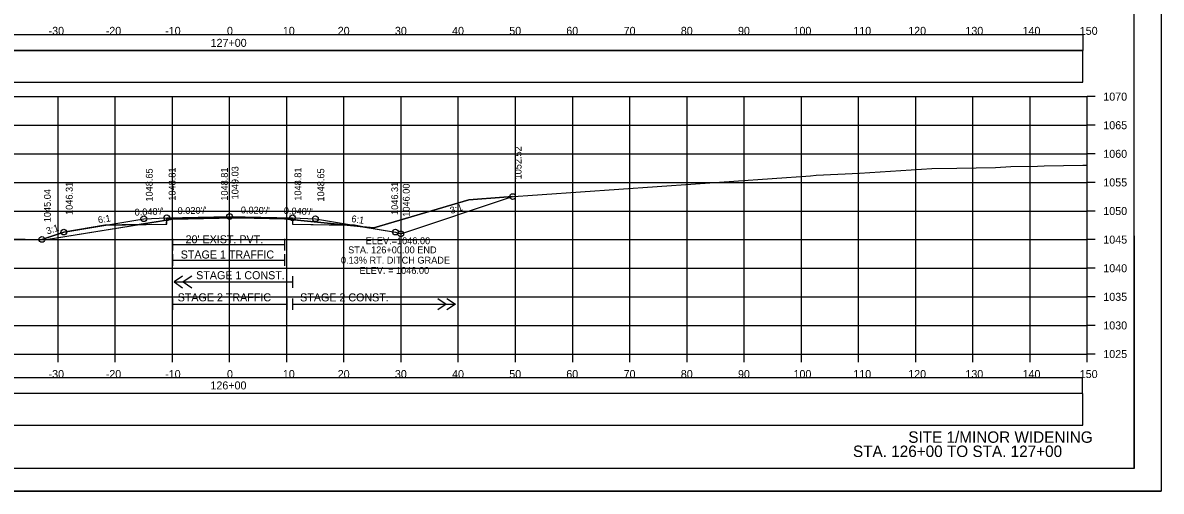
# Model space of a CAD drawing. Extents: x 1370565 to 1374448, y 301010 to 304637.
# Drawn here: x 1370698.9 to 1370898, y 303783.9 to 303865.8 of the extents above; entities that cross this region are included whole.
import ezdxf

# ---------------------------------------------------------------- set-up
doc = ezdxf.new("R2010")
doc.units = 0
for name, color, linetype in [('R_Alt Surface', 7, 'Continuous'), ('R_Axis', 7, 'Continuous'), ('R_Axis Annot', 7, 'Continuous'), ('R_Border', 7, 'Continuous'), ('R_Contours', 7, 'Continuous'), ('R_Draft', 7, 'Continuous'), ('R_Drive', 7, 'Continuous'), ('R_Exist Surface', 7, 'Continuous'), ('R_Fin Surface', 7, 'Continuous'), ('R_Grid', 7, 'Continuous'), ('R_No Plot', 7, 'Continuous'), ('R_Water', 7, 'Continuous'), ('R_Xsect Elev', 7, 'Continuous'), ('R_Xsect Slope', 7, 'Continuous')]:
    doc.layers.add(name, color=color, linetype=linetype)

msp = doc.modelspace()

# ---------------------------------------------------------------- linework, layer by layer
at = {"layer": 'R_Alt Surface'}
for points in [[(1370713.19, 303830.38), (1370724.03, 303830.59), (1370724.02, 303830.59), (1370724.03, 303831.51), (1370735.03, 303831.73), (1370746.03, 303831.51), (1370746.04, 303830.59), (1370746.03, 303830.59), (1370756.87, 303830.38)], [(1370726.82, 303821.47), (1370725.32, 303820.47), (1370726.82, 303819.47)], [(1370728.42, 303821.47), (1370726.92, 303820.47), (1370728.42, 303819.47)], [(1370725.32, 303820.47), (1370746.03, 303820.47)], [(1370725.03, 303817.6), (1370725.03, 303815.6)], [(1370745.03, 303817.6), (1370745.03, 303815.6)], [(1370746.03, 303817.6), (1370746.03, 303815.6)], [(1370746.03, 303817.6), (1370746.03, 303815.6)], [(1370771.42, 303817.6), (1370772.92, 303816.6), (1370771.42, 303815.6)], [(1370773.02, 303817.6), (1370774.52, 303816.6), (1370773.02, 303815.6)], [(1370725.03, 303816.6), (1370745.03, 303816.6)], [(1370746.03, 303816.6), (1370774.52, 303816.6)]]:
    msp.add_lwpolyline(points, dxfattribs=at)
at = {"layer": 'R_Axis'}
for p, q in [((1370885.03, 303807.87), (1370885.03, 303852.87)), ((1370886.43, 303852.87), (1370885.03, 303852.87)), ((1370886.43, 303847.87), (1370885.03, 303847.87)), ((1370886.43, 303842.87), (1370885.03, 303842.87)), ((1370886.43, 303837.87), (1370885.03, 303837.87)), ((1370886.43, 303832.87), (1370885.03, 303832.87)), ((1370886.43, 303827.87), (1370885.03, 303827.87)), ((1370886.43, 303822.87), (1370885.03, 303822.87)), ((1370886.43, 303817.87), (1370885.03, 303817.87)), ((1370886.43, 303812.87), (1370885.03, 303812.87)), ((1370585.03, 303807.87), (1370885.03, 303807.87)), ((1370705.03, 303806.47), (1370705.03, 303807.87)), ((1370715.03, 303806.47), (1370715.03, 303807.87)), ((1370725.03, 303806.47), (1370725.03, 303807.87)), ((1370735.03, 303806.47), (1370735.03, 303807.87)), ((1370745.03, 303806.47), (1370745.03, 303807.87)), ((1370755.03, 303806.47), (1370755.03, 303807.87)), ((1370765.03, 303806.47), (1370765.03, 303807.87)), ((1370775.03, 303806.47), (1370775.03, 303807.87)), ((1370785.03, 303806.47), (1370785.03, 303807.87)), ((1370795.03, 303806.47), (1370795.03, 303807.87)), ((1370805.03, 303806.47), (1370805.03, 303807.87)), ((1370815.03, 303806.47), (1370815.03, 303807.87)), ((1370825.03, 303806.47), (1370825.03, 303807.87)), ((1370835.03, 303806.47), (1370835.03, 303807.87)), ((1370845.03, 303806.47), (1370845.03, 303807.87)), ((1370855.03, 303806.47), (1370855.03, 303807.87)), ((1370865.03, 303806.47), (1370865.03, 303807.87)), ((1370875.03, 303806.47), (1370875.03, 303807.87)), ((1370885.03, 303806.47), (1370885.03, 303807.87)), ((1370886.43, 303807.87), (1370885.03, 303807.87))]:
    msp.add_line(p, q, dxfattribs=at)
for points in [[(1370725.02, 303827.99), (1370725.02, 303825.99)], [(1370725.02, 303826.99), (1370744.65, 303826.99)], [(1370744.65, 303827.99), (1370744.65, 303825.99)], [(1370725.02, 303825.3), (1370725.02, 303823.3)], [(1370744.65, 303825.3), (1370744.65, 303823.3)], [(1370725.02, 303824.3), (1370744.65, 303824.3)], [(1370746.03, 303821.47), (1370746.03, 303819.47)]]:
    msp.add_lwpolyline(points, dxfattribs=at)
at = {"layer": 'R_Border'}
for q in [(1370893.21, 303993.33), (1370577.03, 303787.87)]:
    msp.add_line((1370893.21, 303787.87), q, dxfattribs=at)
at = {"layer": 'R_Contours'}
for p, q in [((1370725.02, 303831.53), (1370724.03, 303831.51)), ((1370724.03, 303831.51), (1370724.03, 303831.28)), ((1370724.03, 303831.28), (1370725.02, 303831.44)), ((1370724.03, 303830.59), (1370724.03, 303831.28)), ((1370733.23, 303831.65), (1370725.02, 303831.53)), ((1370725.02, 303831.44), (1370733.23, 303831.64)), ((1370746.03, 303831.51), (1370744.69, 303831.53)), ((1370744.69, 303831.53), (1370746.03, 303831.38)), ((1370746.03, 303831.38), (1370746.03, 303831.51)), ((1370746.03, 303831.38), (1370746.04, 303830.59)), ((1370706.03, 303829.18), (1370702.21, 303827.91)), ((1370713.19, 303830.38), (1370706.03, 303829.18)), ((1370719.19, 303830.5), (1370713.19, 303830.38)), ((1370719.19, 303830.5), (1370724.03, 303830.59)), ((1370746.04, 303830.59), (1370755.65, 303830.4)), ((1370756.87, 303830.38), (1370755.65, 303830.4)), ((1370755.65, 303830.4), (1370756.86, 303830.28)), ((1370756.86, 303830.28), (1370758.35, 303830.13)), ((1370758.35, 303830.13), (1370756.87, 303830.38)), ((1370758.35, 303830.13), (1370764.03, 303829.18))]:
    msp.add_line(p, q, dxfattribs=at)
for points in [[(1370784.53, 303835.39), (1370782.99, 303835.28), (1370776.89, 303834.84), (1370774.9, 303834.22), (1370760.23, 303829.94), (1370758.35, 303830.13)], [(1370764.03, 303829.18), (1370764.97, 303828.87), (1370784.53, 303835.39)], [(1370724.03, 303831.28), (1370721.08, 303830.8), (1370719.19, 303830.5)], [(1370725.02, 303831.44), (1370725.02, 303831.53)], [(1370725.02, 303831.53), (1370725.02, 303831.44)], [(1370733.23, 303831.64), (1370733.23, 303831.65)], [(1370755.65, 303830.4), (1370747.51, 303831.22), (1370746.03, 303831.38)], [(1370702.21, 303827.91), (1370702.93, 303827.9), (1370719.19, 303830.5)], [(1370756.87, 303830.38), (1370756.86, 303830.28)], [(1370756.86, 303830.28), (1370756.87, 303830.38)]]:
    msp.add_lwpolyline(points, dxfattribs=at)
at = {"layer": 'R_Drive'}
for points in [[(1370585.87, 303860.96), (1370884.29, 303860.96), (1370884.29, 303863.67), (1370585.87, 303863.67)], [(1370585.82, 303855.39), (1370884.24, 303855.39), (1370884.24, 303860.91), (1370585.82, 303860.91)], [(1370585.76, 303801.02), (1370884.18, 303801.02), (1370884.18, 303803.73), (1370585.76, 303803.73)], [(1370585.82, 303795.44), (1370884.24, 303795.44), (1370884.24, 303800.96), (1370585.82, 303800.96)]]:
    msp.add_lwpolyline(points, close=True, dxfattribs=at)
at = {"layer": 'R_Exist Surface'}
msp.add_lwpolyline([(1370695.06, 303828.04), (1370701.38, 303827.92), (1370702.93, 303827.9), (1370721.08, 303830.8), (1370725.02, 303831.44), (1370733.23, 303831.64), (1370734.98, 303831.68), (1370736.71, 303831.66), (1370744.65, 303831.53), (1370747.51, 303831.22), (1370760.23, 303829.94), (1370774.9, 303834.22), (1370776.89, 303834.84), (1370782.99, 303835.28), (1370836.64, 303839.03), (1370837.62, 303839.16), (1370845.21, 303839.49), (1370857.86, 303840.3), (1370862.22, 303840.39), (1370868.99, 303840.49), (1370871.68, 303840.67), (1370876.31, 303840.73), (1370877.5, 303840.76), (1370884.24, 303840.89), (1370885.03, 303840.9)], dxfattribs=at)
at = {"layer": 'R_Fin Surface'}
msp.add_lwpolyline([(1370702.21, 303827.91), (1370706.03, 303829.18), (1370720.03, 303831.52), (1370724.03, 303831.68), (1370735.03, 303831.9), (1370746.03, 303831.68), (1370750.03, 303831.52), (1370764.03, 303829.18), (1370764.97, 303828.87), (1370784.53, 303835.39)], dxfattribs=at)
at = {"layer": 'R_Grid'}
for p, q in [((1370585.03, 303852.87), (1370885.03, 303852.87)), ((1370705.03, 303807.87), (1370705.03, 303852.87)), ((1370715.03, 303807.87), (1370715.03, 303852.87)), ((1370725.03, 303807.87), (1370725.03, 303852.87)), ((1370735.03, 303807.87), (1370735.03, 303852.87)), ((1370745.03, 303807.87), (1370745.03, 303852.87)), ((1370755.03, 303807.87), (1370755.03, 303852.87)), ((1370765.03, 303807.87), (1370765.03, 303852.87)), ((1370775.03, 303807.87), (1370775.03, 303852.87)), ((1370785.03, 303807.87), (1370785.03, 303852.87)), ((1370795.03, 303807.87), (1370795.03, 303852.87)), ((1370805.03, 303807.87), (1370805.03, 303852.87)), ((1370815.03, 303807.87), (1370815.03, 303852.87)), ((1370825.03, 303807.87), (1370825.03, 303852.87)), ((1370835.03, 303807.87), (1370835.03, 303852.87)), ((1370845.03, 303807.87), (1370845.03, 303852.87)), ((1370855.03, 303807.87), (1370855.03, 303852.87)), ((1370865.03, 303807.87), (1370865.03, 303852.87)), ((1370875.03, 303807.87), (1370875.03, 303852.87)), ((1370885.03, 303807.87), (1370885.03, 303852.87)), ((1370585.03, 303847.87), (1370885.03, 303847.87)), ((1370585.03, 303842.87), (1370885.03, 303842.87)), ((1370585.03, 303837.87), (1370885.03, 303837.87)), ((1370585.03, 303832.87), (1370885.03, 303832.87)), ((1370585.03, 303827.87), (1370885.03, 303827.87)), ((1370585.03, 303822.87), (1370885.03, 303822.87)), ((1370585.03, 303817.87), (1370885.03, 303817.87)), ((1370585.03, 303812.87), (1370885.03, 303812.87)), ((1370585.03, 303807.87), (1370885.03, 303807.87))]:
    msp.add_line(p, q, dxfattribs=at)
at = {"layer": 'R_No Plot'}
msp.add_line((1370564.63, 303783.89), (1370897.96, 303783.89), dxfattribs=at)
for points in [[(1370564.62, 303997.22), (1370897.96, 303997.22), (1370897.96, 303783.89), (1370564.62, 303783.89)], [(1370810.95, 303993.33), (1370830.57, 303993.33), (1370830.57, 303983.45), (1370846.68, 303983.45), (1370869.88, 303983.45), (1370869.88, 303950.78), (1370893.09, 303950.78), (1370893.21, 303787.87), (1370577.03, 303787.87), (1370577.03, 303993.33)]]:
    msp.add_lwpolyline(points, close=True, dxfattribs=at)
for centre in [(1370784.53, 303835.39), (1370720.03, 303831.52), (1370724.03, 303831.68), (1370735.03, 303831.9), (1370746.03, 303831.68), (1370750.03, 303831.52), (1370706.03, 303829.18), (1370764.03, 303829.18), (1370764.97, 303828.87), (1370702.21, 303827.91)]:
    msp.add_circle(centre, 0.5, dxfattribs=at)
at = {"layer": 'R_Xsect Elev'}
msp.add_line((1370735.03, 303831.68), (1370735.03, 303841.68), dxfattribs=at)

# ---------------------------------------------------------------- texts
at = {"layer": 'R_Axis Annot'}
for s, p in [('-30', (1370703.37, 303863.67)), ('-20', (1370713.37, 303863.67)), ('-10', (1370723.76, 303863.67)), ('0', (1370734.57, 303863.67)), ('10', (1370744.34, 303863.67)), ('20', (1370753.94, 303863.67)), ('30', (1370763.94, 303863.67)), ('40', (1370773.94, 303863.67)), ('50', (1370783.94, 303863.67)), ('60', (1370793.91, 303863.67)), ('70', (1370803.94, 303863.67)), ('80', (1370813.94, 303863.67)), ('90', (1370823.94, 303863.67)), ('100', (1370833.65, 303863.67)), ('110', (1370844.11, 303863.67)), ('120', (1370853.71, 303863.67)), ('130', (1370863.71, 303863.67)), ('140', (1370873.71, 303863.67)), ('150', (1370883.71, 303863.67)), ('127+00', (1370731.71, 303861.57)), ('1070', (1370887.83, 303852.17)), ('1065', (1370887.83, 303847.17)), ('1060', (1370887.83, 303842.17)), ('1055', (1370887.83, 303837.17)), ('1050', (1370887.83, 303832.17)), ("20' EXIST. PVT.", (1370727.33, 303827.23)), ('1045', (1370887.83, 303827.17)), ('1040', (1370887.83, 303822.17)), ('1035', (1370887.83, 303817.17)), ('1030', (1370887.83, 303812.17)), ('1025', (1370887.83, 303807.17)), ('-30', (1370703.37, 303803.67)), ('-20', (1370713.37, 303803.67)), ('-10', (1370723.76, 303803.67)), ('0', (1370734.57, 303803.67)), ('10', (1370744.34, 303803.67)), ('20', (1370753.94, 303803.67)), ('30', (1370763.94, 303803.67)), ('40', (1370773.94, 303803.67)), ('50', (1370783.94, 303803.67)), ('60', (1370793.91, 303803.67)), ('70', (1370803.94, 303803.67)), ('80', (1370813.94, 303803.67)), ('90', (1370823.94, 303803.67)), ('100', (1370833.65, 303803.67)), ('110', (1370844.11, 303803.67)), ('120', (1370853.71, 303803.67)), ('130', (1370863.71, 303803.67)), ('140', (1370873.71, 303803.67)), ('150', (1370883.71, 303803.67)), ('126+00', (1370731.68, 303801.68))]:
    msp.add_text(s, height=1.4, dxfattribs=at).set_placement(p)
at = {"layer": 'R_Draft'}
for s, p in [('SITE 1/MINOR WIDENING', (1370853.72, 303792.35)), ('STA. 126+00 TO STA. 127+00', (1370844.05, 303789.87))]:
    msp.add_text(s, height=2, dxfattribs=at).set_placement(p)
at = {"layer": 'R_Water'}
for s, p in [('STAGE 1 TRAFFIC', (1370726.48, 303824.57)), ('STAGE 1 CONST.', (1370729.18, 303820.95)), ('STAGE 2 TRAFFIC', (1370725.95, 303817.08)), ('STAGE 2 CONST.', (1370747.37, 303817.07))]:
    msp.add_text(s, height=1.4, dxfattribs=at).set_placement(p)
at = {"layer": 'R_Xsect Elev'}
for s, p in [('1052.52', (1370786.08, 303838.39)), ('1049.03', (1370736.58, 303834.9)), ('1048.65', (1370721.58, 303834.52)), ('1048.81', (1370725.58, 303834.68)), ('1048.81', (1370734.73, 303834.68)), ('1048.81', (1370747.58, 303834.68)), ('1048.65', (1370751.58, 303834.52)), ('1045.04', (1370703.76, 303830.91)), ('1046.31', (1370707.58, 303832.18)), ('1046.31', (1370764.5, 303832.18)), ('1046.00', (1370766.52, 303831.87))]:
    msp.add_text(s, height=1.2, rotation=90, dxfattribs=at).set_placement(p)
for s, p in [('STA. 126+00.00 END ', (1370755.76, 303825.48)), ('ELEV.=1046.00', (1370758.82, 303827.07)), ('0.13% RT. DITCH GRADE', (1370754.5, 303823.68)), ('ELEV. = 1046.00', (1370757.75, 303821.88))]:
    msp.add_text(s, height=1.2, dxfattribs=at).set_placement(p)
at = {"layer": 'R_Xsect Slope'}
for s, rotation, p in [("0.040'/'", 2.2906, (1370718.44, 303832.05)), ("0.020'/'", 1.1458, (1370725.95, 303832.32)), ("0.020'/'", 358.8542, (1370736.98, 303832.46)), ("0.040'/'", 357.7094, (1370744.49, 303832.34)), ('3:1', 18.4332, (1370773.8, 303832.34)), ('6:1', 9.4642, (1370712.1, 303830.7)), ('6:1', 350.5358, (1370756.26, 303830.98)), ('3:1', 18.4349, (1370703.17, 303828.76))]:
    msp.add_text(s, height=1.2, rotation=rotation, dxfattribs=at).set_placement(p)

doc.saveas('drawing.dxf')
